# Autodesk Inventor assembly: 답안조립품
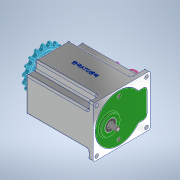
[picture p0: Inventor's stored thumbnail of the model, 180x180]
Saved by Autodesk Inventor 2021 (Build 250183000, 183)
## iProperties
Created: 2022-08
Part Number: 답안조립품
Document SubType Name: Assembly
Designer: Owner
Author: Owner
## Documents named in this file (16)
- C:\Users\Owner\Desktop\720810V1019\답안조립품.iam
- C:\Users\Owner\Desktop\720810V1019\본체.ipt
- C:\Users\Owner\Desktop\720810V1019\커버.ipt
- C:\Users\Owner\Desktop\720810V1019\베어링 608.ipt
- C:\Users\Owner\Desktop\720810V1019\메인 축.ipt
- C:\Users\Owner\Desktop\720810V1019\서브 축.ipt
- C:\Users\Owner\Desktop\720810V1019\베어링 6003.ipt
- C:\Users\Owner\Desktop\720810V1019\오일 실 17 x 32 x 8.ipt
- C:\Users\Owner\Desktop\720810V1019\오일 실 8 x 22 x 7.ipt
- C:\Users\Owner\Desktop\720810V1019\키 5 x 5.ipt
- C:\Users\Owner\Desktop\720810V1019\스프로킷.ipt
- C:\Users\Owner\Desktop\720810V1019\멈춤나사 M3.ipt
- C:\Users\Owner\Desktop\720810V1019\상부 캡.ipt
- C:\Users\Owner\Desktop\720810V1019\부시.ipt
- C:\Users\Owner\Desktop\720810V1019\슬라이더.ipt
- C:\Users\Owner\Desktop\720810V1019\볼트 M4 x 10.ipt
